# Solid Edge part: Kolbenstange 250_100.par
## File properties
Username: ahadarics
Dokumentum tartalom típus: 0
Author: ahadarics
Last saved by: ahadarics
Revision: 82
Sűrűség: 0,000 kg/m^3
Pontosság: 0,990
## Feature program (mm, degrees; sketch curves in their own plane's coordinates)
base feature "unnamed BaseFeature 1"
thread "unnamed Thread 1"
chamfer "Letörés_1"  SetBackValue2 = 20 deg
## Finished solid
Body 1: solid body, 19 faces, 27 edges, 11 vertices.
  Faces by surface: plane 8, cylinder 5, cone 3, torus 3
  Edges by curve: circle 15, line 7, curve on surface 3, ellipse 2
Bounding box of the edges (mm; curved faces can reach further): 250.000 x 250.000 x 429.000, from (-125, -125, -197) to (125, 125, 232).
Cylindrical faces by radius (mm): R19.4 x1, R21 x1, R24.5 x1, R25 x1, R125 x1
Conical faces (half-angle, radius in mm at the cone's reference point): 20 deg R21 x1, 30 deg R24.75 x1, 60 deg R20.2 x1
Toroidal faces (ring radius, tube radius in mm): R20.2 r0.8 x2, R22.5 r2 x1
Planar faces by outward normal: +x 1, +z 3, -x 1, -z 1, oblique 2
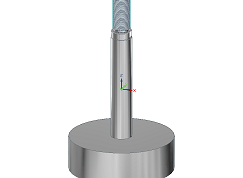
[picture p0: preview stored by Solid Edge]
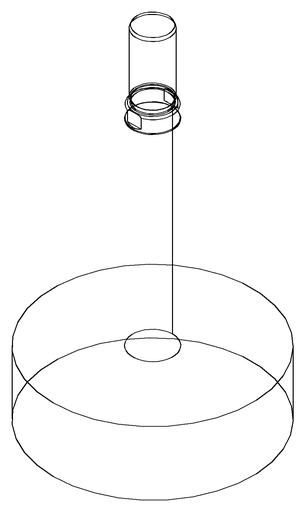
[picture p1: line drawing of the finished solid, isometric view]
